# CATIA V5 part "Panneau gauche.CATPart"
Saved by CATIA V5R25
Part number: Panneau gauche
Bounding box of the stored display mesh (mm): x -55 to 55, y -20 to 20, z 0 to 3
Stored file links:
  C:\Users\m000605\Desktop\Projet FAB liseuse\Panneau gauche.CATPart
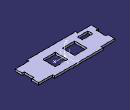
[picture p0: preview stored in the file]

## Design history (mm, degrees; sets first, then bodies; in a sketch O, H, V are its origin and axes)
AxisSystem1: origin (0, 0, 0), X (1, 0, 0), Y (0, 1, 0), Z (0, 0, 1)
Set1
  Sketch1 on XY plane of AxisSystem1, origin (0, 0, 0), H (1, 0, 0), V (0, 1, 0)
    line L1 (-52, 7) -> (-52, -7)
    line L2 (-52, -7) -> (-55, -7)
    line L3 (-35, -17) -> (-35, -20)
    line L4 (-35, -20) -> (35, -20)
    line L5 (35, -20) -> (35, -17)
    point P8 (55, -7)
    line L6 (55, -7) -> (52, -7)
    line L7 (52, -7) -> (52, 7)
    line L8 (52, 7) -> (55, 7)
    point P12 (35, 17)
    line L9 (35, 17) -> (35, 20)
    line L10 (-35, 20) -> (35, 20)
    line L11 (-35, 20) -> (-35, 17)
    line L12 (-55, 7) -> (-52, 7)
    reference intersected line E1 through (0, 0) direction (-1, 0) from ZX plane of AxisSystem1
    reference projected line E2 through (0, 0) direction (1, 0) from edge [XY plane of AxisSystem1 | ZX plane of AxisSystem1]
    line L13 (-35, -17) -> (-55, -17)
    line L14 (-55, -17) -> (-55, -7)
    line L15 (-55, 7) -> (-55, 17)
    line L16 (-55, 17) -> (-35, 17)
    line L17 (35, 17) -> (55, 17)
    line L18 (55, 17) -> (55, 7)
    line L19 (35, -17) -> (55, -17)
    point P20 (55, -17)
    line L20 (55, -17) -> (55, -7)
    reference intersected line E3 through (0, 0) direction (-1, 0) from ZX plane of AxisSystem1
    reference intersected line E4 through (0, 0) direction (0, 1) from YZ plane of AxisSystem1
    reference intersected line E5 through (0, 0) direction (0, 1) from YZ plane of AxisSystem1
    distance L4 L10 = 40
    distance L18 L15 = 110
    distance L10 L17 = 3
    distance L13 L4 = 3
    distance L7 L18 = 3
    distance L19 L6 = 10
    distance L11 L9 = 70
    vertical: L1 V, L3 V, L5 V, L7 V, L9 V, L11 V, L14 V, L15 V, L18 V, L20 V
    horizontal: L2 H, L4 H, L6 H, L8 H, L10 H, L12 H, L13 H, L16 H, L17 H, L19 H
    coincidence: P8 L2, P12 L5, P20 L18
    symmetry: L1 L7 V, L4 L10 E1, L2 L12 H, L8 L6 E2, L15 L18 V, L20 L14 V, L19 L17 H, L13 L16 E3, L11 L9 E4, L3 L5 E5
Body1 (main body)
  Pad1: profile Sketch1, direction (0, 0, 1), length 3
  Sketch2 on end face of Pad1, origin (0, 0, 3), H (1, 0, 0), V (0, 1, 0)
    line L1 (5, 9) -> (23, 9)
    line L2 (23, 9) -> (23, -9)
    line L3 (23, -9) -> (5, -9)
    line L4 (5, -9) -> (5, 9)
    point P5 (-5, 9)
    line L5 (-5, 9) -> (-23, 9)
    line L6 (-23, 9) -> (-23, -9)
    line L7 (-23, -9) -> (-5, -9)
    line L8 (-5, -9) -> (-5, 9)
    point P7 (-23, -9)
    reference intersected line E1 through (0, 0) direction (-1, 0) from ZX plane of AxisSystem1
    reference intersected line E2 through (0, 0) direction (0, 1) from YZ plane of AxisSystem1
    line L9 (-45, -5) -> (-30, -5)
    line L10 (-30, -5) -> (-30, -12)
    line L11 (-30, -12) -> (-45, -12)
    line L12 (-45, -12) -> (-45, -5)
    reference projected line E3 (-52, 7) -> (-52, -7) from edge [face of Pad1 from Sketch1.L1 | end face of Pad1]
    reference projected line E4 (-55, -17) -> (-35, -17) from edge [face of Pad1 from Sketch1.L13 | end face of Pad1]
    length L1 = 18
    length L2 = 18
    distance L8 L4 = 10
    length L9 = 15
    distance L12 E3 = 7
    distance E4 L11 = 5
    distance L11 L9 = 7
    horizontal: L1 H, L3 H, L5 H, L7 H, L9 H, L11 H
    vertical: L2 V, L4 V, L6 V, L8 V, L10 V, L12 V
    coincidence: P5 L1, P7 L3
    symmetry: L8 L4 V, L1 L3 E1, L6 L2 E2
  Pocket1: profile Sketch2, direction (0, 0, -1), length 3
  Sketch3 on end face of Pad1, origin (0, 0, 3), H (1, 0, 0), V (0, 1, 0)
    line L1 (-52, 7) -> (-52, -7)
    line L2 (-52, -7) -> (-55, -7)
    line L3 (-35, -17) -> (-35, -20)
    line L4 (-35, -20) -> (35, -20)
    line L5 (35, -20) -> (35, -17)
    point P8 (55, -7)
    line L6 (55, -7) -> (52, -7)
    line L7 (52, -7) -> (52, 7)
    line L8 (52, 7) -> (55, 7)
    point P12 (35, 17)
    line L9 (35, 17) -> (35, 20)
    line L10 (-35, 20) -> (35, 20)
    line L11 (-35, 20) -> (-35, 17)
    line L12 (-55, 7) -> (-52, 7)
    reference intersected line E1 through (0, 0) direction (-1, 0) from ZX plane of AxisSystem1
    reference projected line E2 through (0, 0) direction (1, 0) from edge [XY plane of AxisSystem1 | ZX plane of AxisSystem1]
    line L13 (-35, -17) -> (-55, -17)
    line L14 (-55, -17) -> (-55, -7)
    line L15 (-55, 7) -> (-55, 17)
    line L16 (-55, 17) -> (-35, 17)
    line L17 (35, 17) -> (55, 17)
    line L18 (55, 17) -> (55, 7)
    line L19 (35, -17) -> (55, -17)
    point P20 (55, -17)
    line L20 (55, -17) -> (55, -7)
    reference intersected line E3 through (0, 0) direction (-1, 0) from ZX plane of AxisSystem1
    reference intersected line E4 through (0, 0) direction (0, 1) from YZ plane of AxisSystem1
    reference intersected line E5 through (0, 0) direction (0, 1) from YZ plane of AxisSystem1
    distance L4 L10 = 40
    distance L18 L15 = 110
    distance L10 L17 = 3
    distance L13 L4 = 3
    distance L7 L18 = 3
    distance L19 L6 = 10
    distance L11 L9 = 70
    vertical: L1 V, L3 V, L5 V, L7 V, L9 V, L11 V, L14 V, L15 V, L18 V, L20 V
    horizontal: L2 H, L4 H, L6 H, L8 H, L10 H, L12 H, L13 H, L16 H, L17 H, L19 H
    coincidence: P8 L2, P12 L5, P20 L18
    symmetry: L1 L7 V, L4 L10 E1, L2 L12 H, L8 L6 E2, L15 L18 V, L20 L14 V, L19 L17 H, L13 L16 E3, L11 L9 E4, L3 L5 E5
  Pad2: profile Sketch3, direction (0, 0, 1), length 3
Current feature: Pocket1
